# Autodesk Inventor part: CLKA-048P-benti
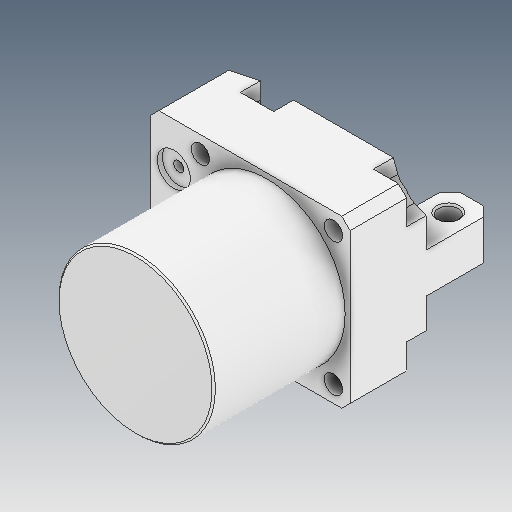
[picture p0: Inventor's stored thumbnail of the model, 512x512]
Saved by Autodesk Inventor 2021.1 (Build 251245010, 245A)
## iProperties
Created: 2021-06
Part Number: CLKA-048P-benti
Material: Ogólny
Document SubType Name: Modeling
Designer: user
Density: 1 g/cm^3
Appearance: Domyślna
Author: user
Revision Number: ÈÎºÎ
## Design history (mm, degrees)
feature "ÇÐ³ý-Ðý×ª6"
node "Bryła1"
